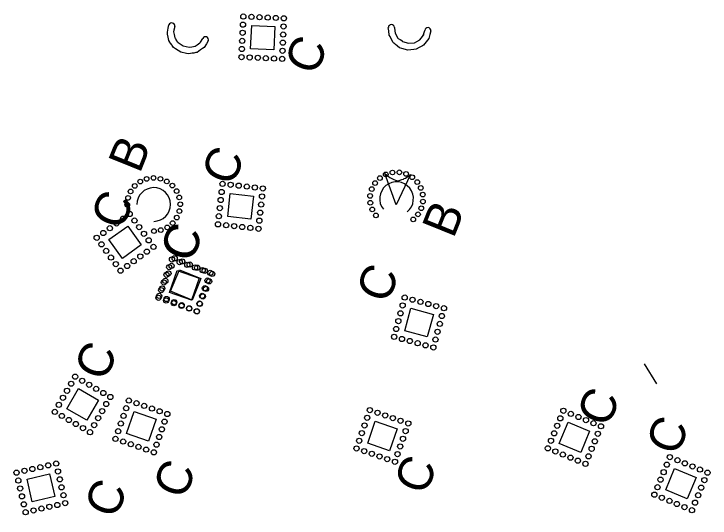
# Model space of a CAD drawing. Extents: x 2470000 to 2520000, y 340000 to 380000.
# Drawn here: x 2483379.1 to 2483678.8, y 368950 to 369167.2 of the extents above; entities that cross this region are included whole.
import ezdxf

# ---------------------------------------------------------------- set-up
doc = ezdxf.new("R2010")
doc.units = 0
for name, color, linetype in [('Coir Fiber Wattle with PAM Both CELL', 7, 'Continuous'), ('Label B Final CELL', 7, 'Continuous'), ('Label C CG CELL', 7, 'Continuous'), ('Prop Guardrail', 7, 'Continuous'), ('Rock Inlet Sediment Trap Type B CG CELL', 7, 'Continuous'), ('Rock Inlet Sediment Trap Type C CG CELL', 7, 'Continuous'), ('Rock Pipe Inlet Sediment Trap Type A Final CELL', 7, 'Continuous'), ('Rock Silt Check Type B CG CELL', 7, 'Continuous'), ('Scratch_Level_5', 7, 'Continuous'), ('Temporary Silt Fence Final', 7, 'Continuous'), ('Wattle Both CELL', 7, 'Continuous'), ('Wattle Final CELL', 7, 'Continuous')]:
    doc.layers.add(name, color=color, linetype=linetype)

# ---------------------------------------------------------------- blocks, each defined once
blk = doc.blocks.new('C3')
at = {"layer": 'Prop Guardrail'}
blk.add_text('C', height=0.3, dxfattribs=at).set_placement((-0.161, -0.136))
blk = doc.blocks.new('C1')
at = {"layer": 'Label C CG CELL'}
blk.add_text('C', height=0.3, dxfattribs=at).set_placement((-0.161, -0.136))
blk = doc.blocks.new('B3')
at = {"layer": 'Label B Final CELL'}
blk.add_text('B', height=0.3, dxfattribs=at).set_placement((-0.1057, -0.151))

msp = doc.modelspace()

# ---------------------------------------------------------------- linework, layer by layer
at = {"layer": 'Coir Fiber Wattle with PAM Both CELL'}
msp.add_line((2483536.66, 368981.94), (2483536.66, 368981.94), dxfattribs=at)
at = {"layer": 'Rock Inlet Sediment Trap Type B CG CELL'}
msp.add_lwpolyline([(2483401.88, 368997.16), (2483406.88, 369005.82), (2483415.54, 369000.82), (2483410.53, 368992.17)], close=True, dxfattribs=at)
for centre in [(2483405.49, 369010.95), (2483408.52, 369009.19), (2483403.74, 369007.91), (2483411.55, 369007.44), (2483414.58, 369005.69), (2483401.99, 369004.88), (2483417.61, 369003.94), (2483400.24, 369001.85), (2483420.64, 369002.19), (2483398.49, 368998.82), (2483418.89, 368999.16), (2483396.74, 368995.79), (2483399.77, 368994.04), (2483417.14, 368996.13), (2483402.8, 368992.29), (2483405.83, 368990.54), (2483415.39, 368993.1), (2483408.86, 368988.79), (2483413.64, 368990.07), (2483411.89, 368987.04)]:
    msp.add_circle(centre, 1.12, dxfattribs=at)
at = {"layer": 'Rock Inlet Sediment Trap Type C CG CELL'}
for points in [[(2483481.05, 369152.17), (2483481.49, 369162.16), (2483491.48, 369161.73), (2483491.03, 369151.74)], [(2483471.16, 369079.91), (2483472.27, 369089.85), (2483482.21, 369088.73), (2483481.08, 369078.8)], [(2483446.57, 369047.76), (2483450.38, 369057.01), (2483459.63, 369053.19), (2483455.8, 369043.95)], [(2483613.91, 368982.13), (2483617.73, 368991.37), (2483626.97, 368987.55), (2483623.14, 368978.32)], [(2483659.76, 368962.15), (2483663.57, 368971.39), (2483672.82, 368967.58), (2483668.99, 368958.34)]]:
    msp.add_lwpolyline(points, close=True, dxfattribs=at)
for centre in [(2483477.89, 369166.07), (2483481.39, 369165.92), (2483484.88, 369165.76), (2483488.38, 369165.61), (2483491.88, 369165.46), (2483495.37, 369165.3), (2483477.74, 369162.57), (2483495.22, 369161.81), (2483477.58, 369159.08), (2483495.07, 369158.31), (2483477.43, 369155.58), (2483494.91, 369154.81), (2483477.28, 369152.08), (2483494.76, 369151.32), (2483477.13, 369148.58), (2483480.62, 369148.43), (2483484.12, 369148.28), (2483487.62, 369148.13), (2483491.11, 369147.97), (2483494.61, 369147.82), (2483468.94, 369093.99), (2483472.42, 369093.6), (2483475.9, 369093.21), (2483479.38, 369092.82), (2483482.86, 369092.43), (2483468.55, 369090.51), (2483486.33, 369092.04), (2483468.16, 369087.03), (2483485.94, 369088.56), (2483467.77, 369083.55), (2483485.55, 369085.08), (2483485.17, 369081.6), (2483467.38, 369080.07), (2483484.78, 369078.12), (2483466.99, 369076.59), (2483470.47, 369076.2), (2483473.95, 369075.81), (2483477.43, 369075.42), (2483480.91, 369075.04), (2483484.39, 369074.65), (2483448.33, 369061.9), (2483451.56, 369060.57), (2483454.8, 369059.23), (2483446.99, 369058.67), (2483458.03, 369057.9), (2483461.27, 369056.56), (2483445.66, 369055.43), (2483464.5, 369055.22), (2483444.32, 369052.2), (2483463.17, 369051.99), (2483442.99, 369048.96), (2483461.83, 369048.75), (2483441.65, 369045.73), (2483444.88, 369044.39), (2483460.5, 369045.52), (2483448.12, 369043.06), (2483451.35, 369041.72), (2483459.16, 369042.28), (2483454.59, 369040.38), (2483457.82, 369039.05), (2483615.67, 368996.27), (2483618.91, 368994.93), (2483622.14, 368993.6), (2483614.34, 368993.03), (2483625.38, 368992.26), (2483628.61, 368990.92), (2483613, 368989.8), (2483631.85, 368989.59), (2483611.66, 368986.56), (2483630.51, 368986.35), (2483610.33, 368983.33), (2483629.17, 368983.12), (2483608.99, 368980.09), (2483612.23, 368978.76), (2483627.84, 368979.88), (2483615.46, 368977.42), (2483618.7, 368976.09), (2483626.5, 368976.65), (2483661.52, 368976.29), (2483621.93, 368974.75), (2483625.17, 368973.41), (2483660.18, 368973.06), (2483664.76, 368974.96), (2483667.99, 368973.62), (2483658.85, 368969.82), (2483671.23, 368972.28), (2483674.46, 368970.95), (2483677.7, 368969.61), (2483657.51, 368966.59), (2483676.36, 368966.38), (2483656.18, 368963.35), (2483675.02, 368963.14), (2483654.84, 368960.12), (2483658.07, 368958.78), (2483661.31, 368957.45), (2483673.69, 368959.91), (2483664.54, 368956.11), (2483667.78, 368954.77), (2483672.35, 368956.67), (2483671.01, 368953.44)]:
    msp.add_circle(centre, 1.12, dxfattribs=at)
at = {"layer": 'Rock Pipe Inlet Sediment Trap Type A Final CELL'}
for centre in [(2483542.09, 369098.89), (2483545.07, 369098.96), (2483436.27, 369096.11), (2483439.22, 369096.53), (2483442.18, 369096.16), (2483536.68, 369096.5), (2483539.22, 369098.05), (2483547.97, 369098.26), (2483550.58, 369096.83), (2483431.17, 369093.11), (2483433.52, 369094.95), (2483444.95, 369095.04), (2483447.33, 369093.25), (2483534.62, 369094.34), (2483552.74, 369094.77), (2483429.38, 369090.73), (2483449.16, 369090.9), (2483533.19, 369091.72), (2483554.3, 369092.23), (2483555.14, 369089.36), (2483428.26, 369087.96), (2483450.33, 369088.15), (2483532.49, 369088.82), (2483555.21, 369086.38), (2483427.9, 369085), (2483450.74, 369085.2), (2483532.56, 369085.84), (2483554.51, 369083.48), (2483450.38, 369082.24), (2483533.4, 369082.98), (2483534.95, 369080.43), (2483553.08, 369080.87), (2483449.26, 369079.47), (2483551.02, 369078.71), (2483445.12, 369075.26), (2483447.47, 369077.09), (2483439.42, 369073.68), (2483442.37, 369074.09)]:
    msp.add_circle(centre, 1.01, dxfattribs=at)
for centre, start, end in [((2483543.85, 369087.6), 308.8812, 218.8723), ((2483439.32, 369085.1), 270.4946, 180.4858)]:
    msp.add_arc(centre, 7.26, start, end, dxfattribs=at)
at = {"layer": 'Rock Silt Check Type B CG CELL'}
msp.add_lwpolyline([(2483549.82, 369098.02), (2483543.73, 369084.97), (2483538.84, 369098.5), (2483539.46, 369097.92), (2483540.22, 369097.24), (2483540.95, 369096.74), (2483541.48, 369096.43), (2483542.66, 369095.88), (2483543.41, 369095.6), (2483544.19, 369095.31), (2483545.02, 369095.47), (2483546.13, 369095.83), (2483546.82, 369096.08), (2483547.18, 369096.28), (2483547.66, 369096.51), (2483548.27, 369096.85), (2483548.78, 369097.21), (2483549.41, 369097.68)], close=True, dxfattribs=at)
at = {"layer": 'Scratch_Level_5'}
for points in [[(2483425.87, 369061.85), (2483420.02, 369069.96), (2483428.13, 369075.81), (2483433.97, 369067.69)], [(2483446.17, 369047.22), (2483449.47, 369056.66), (2483458.91, 369053.35), (2483455.59, 369043.92)], [(2483547.42, 369030.76), (2483550.03, 369040.41), (2483559.69, 369037.8), (2483557.06, 369028.15)], [(2483427.65, 368986.47), (2483430.96, 368995.91), (2483440.39, 368992.6), (2483437.08, 368983.17)], [(2483531.42, 368982.34), (2483534.7, 368991.78), (2483544.15, 368988.5), (2483540.85, 368979.06)], [(2483387, 368957.07), (2483384.77, 368966.82), (2483394.52, 368969.06), (2483396.74, 368959.31)]]:
    msp.add_lwpolyline(points, close=True, dxfattribs=at)
for centre in [(2483428.96, 369081.03), (2483426.12, 369078.98), (2483431.01, 369078.19), (2483420.45, 369074.88), (2483423.29, 369076.93), (2483433.06, 369075.35), (2483417.61, 369072.83), (2483435.11, 369072.51), (2483414.77, 369070.78), (2483437.16, 369069.68), (2483416.82, 369067.95), (2483439.21, 369066.84), (2483418.87, 369065.11), (2483420.92, 369062.27), (2483433.53, 369062.74), (2483436.37, 369064.79), (2483422.97, 369059.43), (2483430.69, 369060.69), (2483447.16, 369061.43), (2483450.46, 369060.28), (2483425.02, 369056.6), (2483427.85, 369058.64), (2483446, 369058.13), (2483453.76, 369059.12), (2483457.06, 369057.96), (2483460.37, 369056.8), (2483444.84, 369054.83), (2483463.67, 369055.65), (2483443.68, 369051.52), (2483462.51, 369052.34), (2483442.53, 369048.22), (2483461.36, 369049.04), (2483441.37, 369044.92), (2483460.2, 369045.74), (2483547.37, 369045.01), (2483444.67, 369043.76), (2483447.98, 369042.6), (2483451.28, 369041.45), (2483459.04, 369042.43), (2483546.46, 369041.63), (2483550.75, 369044.09), (2483554.13, 369043.18), (2483557.51, 369042.27), (2483560.89, 369041.35), (2483454.58, 369040.29), (2483457.89, 369039.13), (2483545.54, 369038.25), (2483564.27, 369040.44), (2483563.35, 369037.06), (2483544.63, 369034.87), (2483562.44, 369033.68), (2483543.72, 369031.49), (2483561.52, 369030.3), (2483542.8, 369028.11), (2483546.18, 369027.2), (2483549.56, 369026.29), (2483560.61, 369026.92), (2483552.94, 369025.37), (2483556.32, 369024.46), (2483559.7, 369023.55), (2483428.64, 369000.68), (2483431.94, 368999.53), (2483427.48, 368997.38), (2483435.24, 368998.37), (2483438.55, 368997.21), (2483532.37, 368996.55), (2483426.32, 368994.08), (2483441.85, 368996.05), (2483445.15, 368994.9), (2483535.68, 368995.41), (2483538.98, 368994.26), (2483425.17, 368990.77), (2483444, 368991.59), (2483531.22, 368993.25), (2483542.29, 368993.11), (2483545.59, 368991.96), (2483548.9, 368990.81), (2483424.01, 368987.47), (2483442.84, 368988.29), (2483530.07, 368989.94), (2483547.75, 368987.5), (2483441.68, 368984.99), (2483528.92, 368986.64), (2483422.85, 368984.17), (2483426.15, 368983.01), (2483429.46, 368981.85), (2483440.52, 368981.68), (2483527.77, 368983.33), (2483546.6, 368984.2), (2483432.76, 368980.7), (2483436.06, 368979.54), (2483439.37, 368978.38), (2483526.62, 368980.02), (2483529.93, 368978.87), (2483545.45, 368980.89), (2483533.24, 368977.73), (2483536.54, 368976.58), (2483539.85, 368975.43), (2483544.3, 368977.59), (2483393.91, 368972.75), (2483397.32, 368973.54), (2483543.16, 368974.28), (2483380.26, 368969.63), (2483383.67, 368970.41), (2483387.08, 368971.19), (2483390.49, 368971.97), (2483398.1, 368970.12), (2483398.88, 368966.71), (2483381.04, 368966.22), (2483399.66, 368963.3), (2483381.82, 368962.81), (2483382.6, 368959.39), (2483400.44, 368959.89), (2483383.39, 368955.98), (2483394.4, 368954.91), (2483397.81, 368955.7), (2483401.23, 368956.48), (2483384.17, 368952.57), (2483387.58, 368953.35), (2483390.99, 368954.13)]:
    msp.add_circle(centre, 1.12, dxfattribs=at)
at = {"layer": 'Temporary Silt Fence Final'}
msp.add_line((2483655.9, 369007.8), (2483650.59, 369016.54), dxfattribs=at)
at = {"layer": 'Wattle Both CELL'}
for p, q in [((2483542.97, 369161.38), (2483543.11, 369159.83)), ((2483543.11, 369159.83), (2483543.19, 369159.04)), ((2483555.51, 369158.3), (2483556.01, 369160.09)), ((2483543.19, 369159.04), (2483543.71, 369158.07)), ((2483543.71, 369158.07), (2483544.41, 369156.8)), ((2483544.59, 369156.66), (2483544.41, 369156.8)), ((2483544.59, 369156.66), (2483545.48, 369155.99)), ((2483553.88, 369156), (2483554.51, 369156.81)), ((2483554.51, 369156.81), (2483555.42, 369157.98)), ((2483555.51, 369158.3), (2483555.42, 369157.98)), ((2483546.44, 369155.28), (2483545.48, 369155.99)), ((2483546.44, 369155.28), (2483548.98, 369154.59)), ((2483548.99, 369154.59), (2483548.98, 369154.59)), ((2483548.99, 369154.59), (2483551.52, 369154.8)), ((2483551.52, 369154.8), (2483552.6, 369155.34)), ((2483552.6, 369155.34), (2483553.88, 369156))]:
    msp.add_line(p, q, dxfattribs=at)
msp.add_lwpolyline([(2483558.6, 369159.87), (2483558.2, 369158.36), (2483557.73, 369156.61), (2483557.23, 369155.94), (2483556.61, 369155.14), (2483555.52, 369153.72), (2483555.48, 369153.7), (2483555.09, 369153.49), (2483555.03, 369153.45), (2483554.18, 369153), (2483553.6, 369152.69), (2483552.31, 369152), (2483551.27, 369151.89), (2483548.73, 369151.63), (2483548.72, 369151.63), (2483546.18, 369152.35), (2483545.19, 369152.63), (2483544.31, 369153.33), (2483544.12, 369153.48), (2483543.37, 369154.08), (2483542.8, 369154.53), (2483542.66, 369154.64), (2483542.37, 369154.87), (2483542.37, 369154.87), (2483541.66, 369156.21), (2483541.04, 369157.4), (2483540.66, 369158.11), (2483540.47, 369159.86), (2483540.31, 369161.4)], dxfattribs=at)
for centre, radius, start in [((2483541.64, 369161.28), 1.33, 3.9462), ((2483557.31, 369159.98), 1.3, 355.0588)]:
    msp.add_arc(centre, radius, start, 175.0588, dxfattribs=at)
at = {"layer": 'Wattle Final CELL'}
for p, q in [((2483448.03, 369160.18), (2483447.86, 369159.41)), ((2483447.86, 369159.41), (2483448.07, 369158.33)), ((2483448.36, 369161.7), (2483448.03, 369160.18)), ((2483448.07, 369158.33), (2483448.35, 369156.9)), ((2483448.49, 369156.71), (2483448.35, 369156.9)), ((2483448.49, 369156.71), (2483449.14, 369155.81)), ((2483459.4, 369155), (2483460.42, 369156.56)), ((2483449.83, 369154.84), (2483449.14, 369155.81)), ((2483449.83, 369154.84), (2483452.05, 369153.43)), ((2483452.06, 369153.42), (2483452.05, 369153.43)), ((2483452.06, 369153.42), (2483454.54, 369152.86)), ((2483455.73, 369153.06), (2483457.15, 369153.29)), ((2483457.15, 369153.29), (2483458, 369153.88)), ((2483458, 369153.88), (2483459.21, 369154.72)), ((2483459.4, 369155), (2483459.21, 369154.72)), ((2483454.54, 369152.86), (2483455.73, 369153.06))]:
    msp.add_line(p, q, dxfattribs=at)
msp.add_lwpolyline([(2483462.81, 369155.57), (2483461.98, 369154.25), (2483461.01, 369152.72), (2483460.33, 369152.24), (2483459.5, 369151.66), (2483458.03, 369150.63), (2483457.99, 369150.62), (2483457.55, 369150.54), (2483457.48, 369150.52), (2483456.54, 369150.34), (2483455.88, 369150.22), (2483454.44, 369149.95), (2483453.42, 369150.16), (2483450.93, 369150.68), (2483450.92, 369150.68), (2483448.71, 369152.13), (2483447.85, 369152.69), (2483447.22, 369153.63), (2483447.08, 369153.82), (2483446.54, 369154.62), (2483446.14, 369155.23), (2483446.04, 369155.37), (2483445.84, 369155.67), (2483445.83, 369155.68), (2483445.56, 369157.17), (2483445.32, 369158.49), (2483445.18, 369159.28), (2483445.52, 369161.01), (2483445.83, 369162.52)], dxfattribs=at)
for centre, radius, start in [((2483447.06, 369162.01), 1.33, 346.4504), ((2483461.61, 369156.06), 1.3, 337.5631)]:
    msp.add_arc(centre, radius, start, 157.5631, dxfattribs=at)

# ---------------------------------------------------------------- block references
at = {"layer": 'Label B Final CELL', "xscale": 50, "yscale": 50, "rotation": 68.05623472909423}
for p in [(2483428.25, 369105.8), (2483563.3, 369077.82)]:
    msp.add_blockref('B3', p, dxfattribs=at)
at = {"layer": 'Label C CG CELL', "xscale": 50, "yscale": 49.99999999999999, "rotation": 67.56305879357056}
msp.add_blockref('C3', (2483415.28, 369018.44), dxfattribs=at)
at = {"layer": 'Rock Inlet Sediment Trap Type C CG CELL', "xscale": 50, "yscale": 49.99999999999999, "rotation": 67.56305879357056}
for p in [(2483505.82, 369150.21), (2483470.02, 369102.5), (2483452.23, 369069.54), (2483631.64, 368998.62), (2483661.38, 368986.34)]:
    msp.add_blockref('C1', p, dxfattribs=at)
at = {"layer": 'Scratch_Level_5', "xscale": 50, "yscale": 49.99999999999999, "rotation": 67.56305879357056}
for p in [(2483422.34, 369083.51), (2483452.17, 369069.38), (2483536.6, 369051.91), (2483552.92, 368969.4), (2483449.13, 368967.57), (2483419.6, 368959.22)]:
    msp.add_blockref('C3', p, dxfattribs=at)

doc.saveas('drawing.dxf')
